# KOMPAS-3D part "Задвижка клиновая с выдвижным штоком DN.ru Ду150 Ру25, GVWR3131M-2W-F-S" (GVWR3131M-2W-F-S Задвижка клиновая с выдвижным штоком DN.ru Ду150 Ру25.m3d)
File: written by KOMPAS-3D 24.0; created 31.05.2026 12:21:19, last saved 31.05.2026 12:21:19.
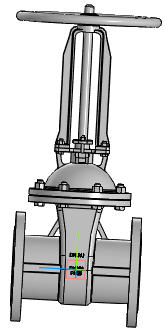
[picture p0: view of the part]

Document properties: Автор: R2D2; Полное имя файла: E:\Работа\Зайцев\GVWR3131M-2W-F-S Задвижка клиновая 30нж64нж DN.ru  Ду50-150 Ру25\исходные данные\DN150\dn150\GVWR3131M-2W-F-S Задвижка клиновая с выдвижным штоком DN.ru Ду150 Ру25.m3d

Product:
- Component [detail]: Деталь2  | qty 1  | pos. 1  | Автор: R2D2; additional columns: Типовые; source file: ..\Деталь2 Деталь2.m3d
- Component [detail]: ANSI B18.2.4.2M - M16x2 - 24  | designation ANSI B18.2.4.2M - M16x2  | qty 8  | pos. 2  | Комментарий: Типы метрических   шестигранных гаек   2; Автор: R2D2; additional columns: Сталь, мягкая; source file: ..\ANSI B18.2.4.2M - M16x2 ANSI B18.2.4.2M - M16x2 - 24.m3d
- Component [detail]: AS 1110 - M16 x 60  | qty 8  | pos. 3  | Комментарий: Болты и винты   шестигранные точные   метрические ISO; Автор: R2D2; additional columns: Сталь, мягкая; source file: ..\AS 1110 - M16 x 60 AS 1110 - M16 x 60.m3d
- Component [detail]: AS 1110 - M10 x 35  | qty 4  | pos. 4  | Комментарий: Болты и винты   шестигранные точные   метрические ISO; Автор: R2D2; additional columns: Сталь, мягкая; source file: ..\AS 1110 - M10 x 35 AS 1110 - M10 x 35.m3d
- Component [detail]: ANSI B18.2.4.2M - M10x1,5 - 16  | designation ANSI B18.2.4.2M - M10x1,5  | qty 4  | pos. 5  | Комментарий: Типы метрических   шестигранных гаек   2; Автор: R2D2; additional columns: Сталь, мягкая; source file: ..\ANSI B18.2.4.2M - M10x1,5 ANSI B18.2.4.2M - M10x1,5 - 16.m3d
- Component [detail]: ANSI B18.2.4.2M - M8x1,25 - 13  | designation ANSI B18.2.4.2M - M8x1,25  | qty 1  | pos. 6  | Комментарий: Типы метрических   шестигранных гаек   2; Автор: R2D2; additional columns: Сталь, мягкая; source file: ..\ANSI B18.2.4.2M - M8x1,25 ANSI B18.2.4.2M - M8x1,25 - 13.m3d
- Component [detail]: Деталь1  | qty 1  | pos. 7  | additional columns: Типовые; source file: ..\2.m3d
- Component [detail]: Деталь1  | qty 1  | pos. 7  | Автор: R2D2; additional columns: Типовые; source file: ..\3.m3d
- Component [detail]: Деталь1  | qty 2  | Автор: R2D2; additional columns: Типовые; source file: ..\1.m3d
- Component [detail]: ANSI B18.2.4.2M - M8x1,25 - 13  | designation ANSI B18.2.4.2M - M8x1,25-01  | qty 1  | pos. 6  | Комментарий: Типы метрических   шестигранных гаек   2; Автор: R2D2; additional columns: Сталь, мягкая; source file: ..\ANSI B18.2.4.2M - M8x1,25 ANSI B18.2.4.2M - M8x1,25 - 13.m3d
- Part/product: Задвижка клиновая с выдвижным штоком DN.ru Ду150 Ру25  | designation GVWR3131M-2W-F-S
    Масса: 61
    Раздел спецификации: Прочие изделия
    Примечание: D040-07877

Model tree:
1. Массив по сетке:2  (labels: Грань.Твердое тело1; Вершина.Твердое тело1)  (4 pattern instances)
     Шаг 1 = 50; Угол раствора = 90; Шаг 2 = 120
2. Массив по концентрической сетке:1  (labels: Грань.Твердое тело1)  (8 pattern instances)
     Шаг 2 = 360
3. Эскиз:1
4. Элемент выдавливания:1  (labels: Грань.Твердое тело1)
     Расстояние 1 = 98.5; Смещение 1 = 1
5. Элемент выдавливания:2  (with: Грань.Элемент выдавливания:1)
     Расстояние 1 = 211
6. Элемент выдавливания:3  (with: Грань.Элемент выдавливания:1, Грань.Элемент вращения:1)
     Расстояние 1 = 38.9829
7. Элемент выдавливания:4  (with: Грань.Элемент выдавливания:1, Грань.Элемент вращения:1)  (labels: Грань.Твердое тело1; Грань.Solid1; Твердое тело1)
     Расстояние 1 = 40.9519; Расстояние = -727.5; Расстояние = -175; Ориентация = 2; Ориентация = 2

Referenced files in E:\Работа\Зайцев\GVWR3131M-2W-F-S Задвижка клиновая 30нж64нж DN.ru  Ду50-150 Ру25\исходные данные\DN150\: Деталь2 Деталь2.m3d, ANSI B18.2.4.2M - M16x2 ANSI B18.2.4.2M - M16x2 - 24.m3d, AS 1110 - M16 x 60 AS 1110 - M16 x 60.m3d, AS 1110 - M10 x 35 AS 1110 - M10 x 35.m3d, ANSI B18.2.4.2M - M10x1,5 ANSI B18.2.4.2M - M10x1,5 - 16.m3d, ANSI B18.2.4.2M - M8x1,25 ANSI B18.2.4.2M - M8x1,25 - 13.m3d, 2.m3d, 3.m3d, 1.m3d
Referenced files in E:\Работа\Зайцев\GVWR3131M-2W-F-S Задвижка клиновая с выдвижным штоком DN.ru Ду50-200 Ру63\DN150\исходные материалы\: 1.m3d, ANSI B18.2.4.2M - M10x1,5 ANSI B18.2.4.2M - M10x1,5 - 16.m3d, AS 1110 - M10 x 35 AS 1110 - M10 x 35.m3d, ANSI B18.2.4.2M - M16x2 ANSI B18.2.4.2M - M16x2 - 24.m3d, AS 1110 - M16 x 60 AS 1110 - M16 x 60.m3d
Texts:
  GVWR3131M-2W-F-S
  DN150
  GOST 26.020 Pr3
  PN25
  Деталь2 Деталь2
  ANSI B18.2.4.2M - M16x2 ANSI B18.2.4.2M - M16x2 - 24 (1)
  AS 1110 - M16 x 60 AS 1110 - M16 x 60 (1)
  AS 1110 - M10 x 35 AS 1110 - M10 x 35 (1)
  ANSI B18.2.4.2M - M10x1,5 ANSI B18.2.4.2M - M10x1,5 - 16 (1)
  ANSI B18.2.4.2M - M8x1,25 ANSI B18.2.4.2M - M8x1,25 - 13
  Деталь1 Деталь1
  Деталь1 Деталь1 (1)
  Деталь1 Деталь1 (2)
  ANSI B18.2.4.2M - M10x1,5 ANSI B18.2.4.2M - M10x1,5 - 16 (2)
  AS 1110 - M10 x 35 AS 1110 - M10 x 35 (2)
  ANSI B18.2.4.2M - M10x1,5 ANSI B18.2.4.2M - M10x1,5 - 16 (3)
  AS 1110 - M10 x 35 AS 1110 - M10 x 35 (3)
  ANSI B18.2.4.2M - M10x1,5 ANSI B18.2.4.2M - M10x1,5 - 16 (4)
  AS 1110 - M10 x 35 AS 1110 - M10 x 35 (4)
  ANSI B18.2.4.2M - M16x2 ANSI B18.2.4.2M - M16x2 - 24 (2)
  AS 1110 - M16 x 60 AS 1110 - M16 x 60 (2)
  ANSI B18.2.4.2M - M16x2 ANSI B18.2.4.2M - M16x2 - 24 (3)
  AS 1110 - M16 x 60 AS 1110 - M16 x 60 (3)
  ANSI B18.2.4.2M - M16x2 ANSI B18.2.4.2M - M16x2 - 24 (4)
  AS 1110 - M16 x 60 AS 1110 - M16 x 60 (4)
  ANSI B18.2.4.2M - M16x2 ANSI B18.2.4.2M - M16x2 - 24 (5)
  AS 1110 - M16 x 60 AS 1110 - M16 x 60 (5)
  ANSI B18.2.4.2M - M16x2 ANSI B18.2.4.2M - M16x2 - 24 (6)
  AS 1110 - M16 x 60 AS 1110 - M16 x 60 (6)
  ANSI B18.2.4.2M - M16x2 ANSI B18.2.4.2M - M16x2 - 24 (7)
  AS 1110 - M16 x 60 AS 1110 - M16 x 60 (7)
  ANSI B18.2.4.2M - M16x2 ANSI B18.2.4.2M - M16x2 - 24 (8)
  AS 1110 - M16 x 60 AS 1110 - M16 x 60 (8)
  ANSI B18.2.4.2M - M8x1,25-01 ANSI B18.2.4.2M - M8x1,25 - 13
  Ось Z.Начало координат
  Ось Y.Начало координат
  Плоскость ZX.Начало координат
  Плоскость ZY.Начало координат
  Плоскость XY.Начало координат
  Solid1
